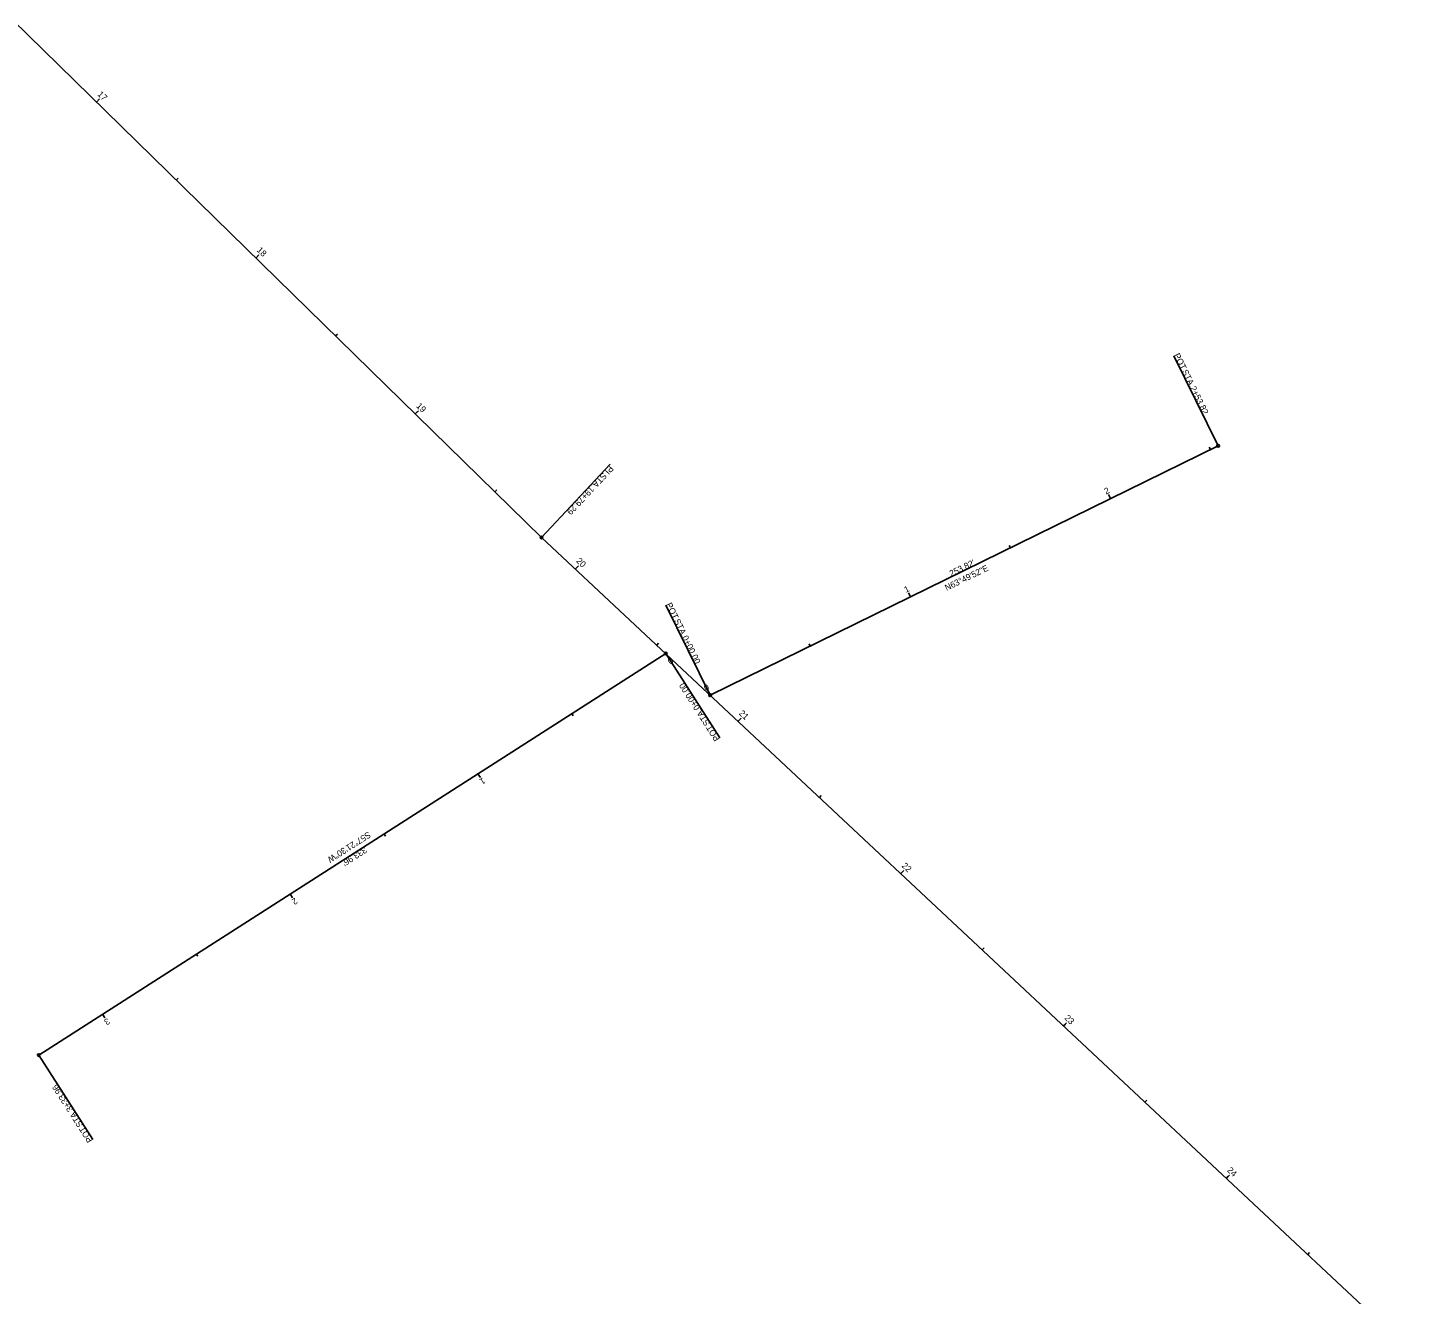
# Model space of a CAD drawing. Extents: x 1478151 to 1480590, y 379063 to 381406.
# Drawn here: x 1479336 to 1479964, y 379650 to 380218 of the extents above; entities that cross this region are included whole.
import ezdxf

# ---------------------------------------------------------------- set-up
doc = ezdxf.new("R2010")
doc.units = 0
for name, color, linetype in [('DV_X_Property_Line', 7, 'Continuous'), ('RW_P_Esmt_SH', 7, 'Continuous'), ('RW_X_Esmt_SH', 7, 'Continuous'), ('RW_X_Fee_RW', 7, 'Continuous'), ('VG_X_Cells', 7, 'Continuous')]:
    doc.layers.add(name, color=color, linetype=linetype)

msp = doc.modelspace()

# ---------------------------------------------------------------- linework, layer by layer
at = {"layer": 'DV_X_Property_Line'}
for p, q in [((1479870.13, 380030.67), (1479850.28, 380071.06)), ((1479566.7, 379989.54), (1479597.46, 380022.39)), ((1479642.33, 379918.73), (1479622.48, 379959.12)), ((1479622.34, 379937.45), (1479646.61, 379899.55)), ((1479341.12, 379757.31), (1479365.39, 379719.42))]:
    msp.add_line(p, q, dxfattribs=at)
for centre in [(1479870.13, 380030.67), (1479566.7, 379989.54), (1479622.34, 379937.45), (1479642.33, 379918.73), (1479341.12, 379757.31)]:
    msp.add_circle(centre, 0.6, dxfattribs=at)
at = {"layer": 'RW_X_Esmt_SH'}
for p, q in [((1478151.68, 381373.49), (1479566.7, 379989.54)), ((1479642.33, 379918.73), (1479870.13, 380030.67)), ((1479566.7, 379989.54), (1480555.97, 379063.33)), ((1479622.34, 379937.45), (1479341.12, 379757.31))]:
    msp.add_line(p, q, dxfattribs=at)
at = {"layer": 'VG_X_Cells'}
for p, q in [((1479367.03, 380184.82), (1479368.43, 380186.25)), ((1479402.78, 380149.86), (1479403.61, 380150.72)), ((1479438.52, 380114.9), (1479439.92, 380116.33)), ((1479438.52, 380114.9), (1479439.36, 380115.76)), ((1479474.27, 380079.94), (1479475.11, 380080.8)), ((1479510.01, 380044.98), (1479511.41, 380046.41)), ((1479510.01, 380044.98), (1479510.85, 380045.84)), ((1479866.7, 380028.99), (1479866.17, 380030.06)), ((1479545.76, 380010.02), (1479546.6, 380010.88)), ((1479821.83, 380006.93), (1479820.94, 380008.73)), ((1479776.95, 379984.88), (1479776.42, 379985.96)), ((1479581.82, 379975.38), (1479583.18, 379976.84)), ((1479581.82, 379975.38), (1479582.64, 379976.26)), ((1479732.08, 379962.83), (1479731.19, 379964.63)), ((1479618.32, 379941.21), (1479619.14, 379942.09)), ((1479687.2, 379940.78), (1479686.67, 379941.86)), ((1479622.34, 379937.45), (1479623.42, 379935.76)), ((1479642.33, 379918.73), (1479641.44, 379920.53)), ((1479580.23, 379910.48), (1479580.88, 379909.47)), ((1479654.81, 379907.04), (1479656.18, 379908.5)), ((1479654.81, 379907.04), (1479655.63, 379907.91)), ((1479538.13, 379883.51), (1479539.21, 379881.82)), ((1479691.31, 379872.87), (1479692.13, 379873.74)), ((1479496.03, 379856.54), (1479496.68, 379855.53)), ((1479727.81, 379838.69), (1479729.18, 379840.15)), ((1479727.81, 379838.69), (1479728.63, 379839.57)), ((1479453.93, 379829.57), (1479455, 379827.88)), ((1479411.82, 379802.6), (1479412.47, 379801.59)), ((1479764.31, 379804.52), (1479765.13, 379805.4)), ((1479369.72, 379775.63), (1479370.8, 379773.95)), ((1479800.81, 379770.35), (1479802.18, 379771.81)), ((1479800.81, 379770.35), (1479801.63, 379771.22)), ((1479837.31, 379736.18), (1479838.13, 379737.05)), ((1479873.81, 379702), (1479875.18, 379703.46)), ((1479873.81, 379702), (1479874.63, 379702.88)), ((1479910.31, 379667.83), (1479911.13, 379668.71))]:
    msp.add_line(p, q, dxfattribs=at)

# ---------------------------------------------------------------- texts
at = {"layer": 'DV_X_Property_Line'}
for s, rotation, p in [('POT', 296.16893, (1479850.18, 380071.35)), (' STA. ', 296.16893, (1479853.32, 380064.95)), ('2+53.82', 296.16893, (1479857.44, 380056.59)), ('PI', 226.88585, (1479597.17, 380022.02)), (' STA. ', 226.88585, (1479594.9, 380019.6)), ('19+79.29', 226.88585, (1479588.53, 380012.79)), ('POT', 296.16893, (1479622.35, 379959.46)), (' STA. ', 296.16893, (1479625.5, 379953.06)), ('0+00.00', 296.16893, (1479629.61, 379944.7)), ('0+00.00', 122.64178, (1479637.9, 379913.08)), (' STA. ', 122.64178, (1479642.93, 379905.23)), ('POT', 122.64178, (1479646.78, 379899.22)), ('3+33.96', 122.64178, (1479356.68, 379732.95)), (' STA. ', 122.64178, (1479361.71, 379725.1)), ('POT', 122.64178, (1479365.55, 379719.1))]:
    msp.add_text(s, height=2.8, rotation=rotation, dxfattribs=at).set_placement(p)
at = {"layer": 'RW_P_Esmt_SH'}
for s, rotation, p in [("253.82'", 26.16893, (1479750.43, 379971.89)), ("333.96'", 212.64178, (1479487.17, 379850.82))]:
    msp.add_text(s, height=2.8, rotation=rotation, dxfattribs=at).set_placement(p)
at = {"layer": 'RW_X_Fee_RW'}
for s, rotation, p in [('N63°49\'52"E', 26.16893, (1479748.37, 379965.49)), ('S57°21\'30"W', 212.64178, (1479488.93, 379857.69))]:
    msp.add_text(s, height=2.8, rotation=rotation, dxfattribs=at).set_placement(p)
at = {"layer": 'VG_X_Cells'}
for s, rotation, p in [('17', 315.63602, (1479367.26, 380188.1)), ('18', 315.63602, (1479438.74, 380118.18)), ('19', 315.63602, (1479510.25, 380048.24)), ('2', 26.16893, (1479819.85, 380008.75)), ('20', 316.88585, (1479581.95, 379978.68)), ('1', 26.16893, (1479730.09, 379964.64)), ('0', 212.64178, (1479624.56, 379935.9)), ('0', 26.16893, (1479640.3, 379920.52)), ('21', 316.88585, (1479654.99, 379910.3)), ('1', 212.64178, (1479540.31, 379881.93)), ('22', 316.88585, (1479727.99, 379841.95)), ('2', 212.64178, (1479456.1, 379827.99)), ('3', 212.64178, (1479371.88, 379774.04)), ('23', 316.88585, (1479801, 379773.6)), ('24', 316.88585, (1479873.94, 379705.31))]:
    msp.add_text(s, height=2.8, rotation=rotation, dxfattribs=at).set_placement(p)

doc.saveas('drawing.dxf')
